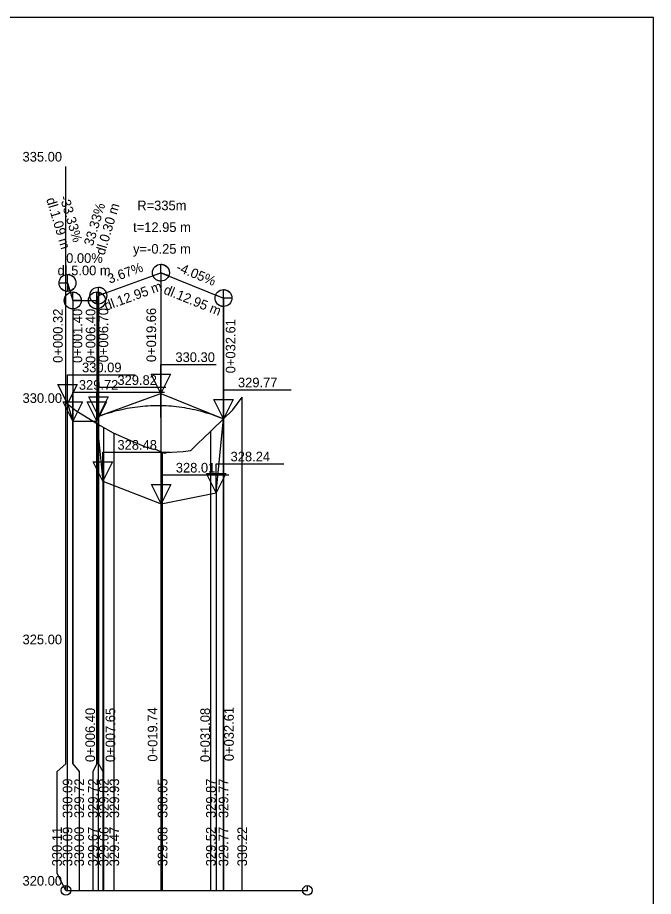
# Model space of a CAD drawing. Extents: x -559854 to -559644, y -1163295 to -1162998.
# Drawn here: x -559776.1 to -559644.4, y -1163179.8 to -1162997.7 of the extents above; entities that cross this region are included whole.
import ezdxf

# ---------------------------------------------------------------- set-up
doc = ezdxf.new("R2010")
doc.units = 0
for name, color, linetype in [('13', 7, 'Continuous'), ('14', 7, 'Continuous'), ('16', 7, 'Continuous'), ('46', 7, 'Continuous'), ('56', 7, 'Continuous'), ('8', 7, 'Continuous'), ('_rám PH2 a PH4', 7, 'Continuous')]:
    doc.layers.add(name, color=color, linetype=linetype)

msp = doc.modelspace()

# ---------------------------------------------------------------- linework, layer by layer
for p, q in [((-559644.4, -1162997.74), (-559854.4, -1162997.74)), ((-559644.4, -1163294.74), (-559644.4, -1162997.74)), ((-559752.86, -1163077.97), (-559746.38, -1163075.59)), ((-559746.38, -1163080.59), (-559746.38, -1163075.59)), ((-559746.38, -1163075.59), (-559739.91, -1163078.22)), ((-559729.55, -1163178.57), (-559729.55, -1163076.37)), ((-559765.72, -1163178.57), (-559765.72, -1163077.67)), ((-559765.72, -1163077.72), (-559764.64, -1163081.34)), ((-559764.64, -1163152.32), (-559764.64, -1163078.57)), ((-559759.64, -1163081.34), (-559759.34, -1163080.34)), ((-559759.34, -1163080.34), (-559759.33, -1163080.34)), ((-559759.34, -1163080.34), (-559759.33, -1163080.34)), ((-559734.96, -1163096.18), (-559733.43, -1163080.84)), ((-559733.43, -1163080.84), (-559733.43, -1163080.84)), ((-559733.43, -1163080.84), (-559733.43, -1163080.84)), ((-559733.43, -1163178.57), (-559733.43, -1163080.87)), ((-559733.43, -1163178.57), (-559733.43, -1163080.87)), ((-559764.64, -1163081.34), (-559759.64, -1163081.34)), ((-559759.64, -1163081.34), (-559758.39, -1163093.77)), ((-559759.64, -1163152.32), (-559759.64, -1163081.87)), ((-559759.34, -1163152.32), (-559759.34, -1163081.97)), ((-559759.33, -1163178.57), (-559759.33, -1163081.97)), ((-559758.22, -1163178.57), (-559758.22, -1163082.68)), ((-559756.04, -1163178.57), (-559756.04, -1163083.87)), ((-559736.04, -1163178.57), (-559736.04, -1163083.37)), ((-559746.04, -1163178.57), (-559746.04, -1163087.77)), ((-559758.39, -1163093.77), (-559746.3, -1163098.49)), ((-559746.3, -1163098.49), (-559734.96, -1163096.18))]:
    msp.add_line(p, q)
for points in [[(-559766.04, -1163077.46), (-559764.01, -1163079.13), (-559758.94, -1163082.26), (-559756.27, -1163083.79), (-559752.18, -1163085.57), (-559749.89, -1163086.54), (-559749.64, -1163086.64), (-559748.19, -1163087.06), (-559747.74, -1163087.12), (-559747.6, -1163087.18), (-559745.64, -1163087.97), (-559745.31, -1163087.88), (-559745.23, -1163087.86), (-559743.02, -1163087.72), (-559741.79, -1163087.63), (-559741.79, -1163087.63), (-559740.73, -1163087.5), (-559740.32, -1163087.45), (-559740.2, -1163087.41), (-559738.44, -1163085.72), (-559737.86, -1163085.17), (-559731.52, -1163078.98), (-559729.55, -1163076.35)], [(-559767.9, -1163153.91), (-559766.04, -1163152.32), (-559766.04, -1163077.47)], [(-559759.33, -1163080.34), (-559758.79, -1163080.15), (-559758.25, -1163079.96), (-559757.71, -1163079.79), (-559757.17, -1163079.62), (-559756.63, -1163079.46), (-559756.09, -1163079.31), (-559755.55, -1163079.17), (-559755.01, -1163079.04), (-559754.47, -1163078.91), (-559753.94, -1163078.8), (-559753.4, -1163078.69), (-559752.86, -1163078.59), (-559752.32, -1163078.5), (-559751.78, -1163078.42), (-559751.24, -1163078.35), (-559750.7, -1163078.29), (-559750.16, -1163078.23), (-559749.62, -1163078.19), (-559749.08, -1163078.15), (-559748.54, -1163078.12), (-559748, -1163078.1), (-559747.46, -1163078.09), (-559746.92, -1163078.09), (-559745.84, -1163078.11), (-559745.3, -1163078.13), (-559744.76, -1163078.16), (-559744.22, -1163078.2), (-559743.68, -1163078.25), (-559743.14, -1163078.31), (-559742.6, -1163078.38), (-559742.06, -1163078.45), (-559741.52, -1163078.54), (-559740.99, -1163078.63), (-559740.45, -1163078.73), (-559739.91, -1163078.84), (-559739.37, -1163078.96), (-559738.83, -1163079.09), (-559738.29, -1163079.22), (-559737.75, -1163079.37), (-559737.21, -1163079.52), (-559736.67, -1163079.68), (-559736.13, -1163079.86), (-559735.59, -1163080.04), (-559735.05, -1163080.22), (-559734.51, -1163080.42), (-559733.97, -1163080.63), (-559733.43, -1163080.84)], [(-559759.33, -1163080.34), (-559758.79, -1163080.15), (-559758.25, -1163079.96), (-559757.71, -1163079.79), (-559757.17, -1163079.62), (-559756.63, -1163079.46), (-559756.09, -1163079.31), (-559755.55, -1163079.17), (-559755.01, -1163079.04), (-559754.47, -1163078.91), (-559753.94, -1163078.8), (-559753.4, -1163078.69), (-559752.86, -1163078.59), (-559752.32, -1163078.5), (-559751.78, -1163078.42), (-559751.24, -1163078.35), (-559750.7, -1163078.29), (-559750.16, -1163078.23), (-559749.62, -1163078.19), (-559749.08, -1163078.15), (-559748.54, -1163078.12), (-559748, -1163078.1), (-559747.46, -1163078.09), (-559746.92, -1163078.09), (-559745.84, -1163078.11), (-559745.3, -1163078.13), (-559744.76, -1163078.16), (-559744.22, -1163078.2), (-559743.68, -1163078.25), (-559743.14, -1163078.31), (-559742.6, -1163078.38), (-559742.06, -1163078.45), (-559741.52, -1163078.54), (-559740.99, -1163078.63), (-559740.45, -1163078.73), (-559739.91, -1163078.84), (-559739.37, -1163078.96), (-559738.83, -1163079.09), (-559738.29, -1163079.22), (-559737.75, -1163079.37), (-559737.21, -1163079.52), (-559736.67, -1163079.68), (-559736.13, -1163079.86), (-559735.59, -1163080.04), (-559735.05, -1163080.22), (-559734.51, -1163080.42), (-559733.97, -1163080.63), (-559733.43, -1163080.84)], [(-559766.04, -1163178.57), (-559767.9, -1163175.05), (-559767.9, -1163153.91)]]:
    msp.add_lwpolyline(points)
for centre in [(-559766.04, -1163178.57), (-559716.04, -1163178.57)]:
    msp.add_circle(centre, 1)
at = {"layer": '14'}
for p, q in [((-559759.34, -1163055.34), (-559746.38, -1163050.59)), ((-559746.38, -1163050.59), (-559746.38, -1163178.57)), ((-559746.38, -1163050.59), (-559733.43, -1163055.84)), ((-559765.72, -1163052.72), (-559765.72, -1163052.72)), ((-559765.72, -1163052.72), (-559764.64, -1163056.34)), ((-559759.64, -1163056.34), (-559759.34, -1163055.34)), ((-559759.34, -1163055.34), (-559759.34, -1163152.32)), ((-559764.64, -1163056.34), (-559764.64, -1163152.32)), ((-559764.64, -1163056.34), (-559759.64, -1163056.34)), ((-559733.43, -1163055.84), (-559733.43, -1163178.57)), ((-559759.34, -1163080.34), (-559746.38, -1163075.59)), ((-559746.38, -1163075.59), (-559746.38, -1163178.57)), ((-559746.38, -1163075.59), (-559733.43, -1163080.84)), ((-559765.72, -1163077.72), (-559764.64, -1163081.34)), ((-559765.72, -1163077.72), (-559764.64, -1163081.34)), ((-559765.72, -1163077.72), (-559765.72, -1163077.72)), ((-559765.72, -1163077.72), (-559764.64, -1163081.34)), ((-559759.64, -1163081.34), (-559759.34, -1163080.34)), ((-559759.64, -1163081.34), (-559759.34, -1163080.34)), ((-559759.64, -1163081.34), (-559759.34, -1163080.34)), ((-559759.34, -1163080.34), (-559759.33, -1163080.34)), ((-559759.34, -1163080.34), (-559759.33, -1163080.34)), ((-559759.34, -1163080.34), (-559759.34, -1163152.32)), ((-559734.96, -1163096.18), (-559733.43, -1163080.84)), ((-559734.96, -1163096.18), (-559733.43, -1163080.84)), ((-559734.96, -1163096.18), (-559733.43, -1163080.84)), ((-559733.43, -1163080.84), (-559733.43, -1163080.84)), ((-559733.43, -1163080.84), (-559733.43, -1163080.84)), ((-559733.43, -1163080.84), (-559733.43, -1163178.57)), ((-559733.43, -1163080.84), (-559733.43, -1163178.57)), ((-559764.64, -1163081.34), (-559759.64, -1163081.34)), ((-559764.64, -1163081.34), (-559759.64, -1163081.34)), ((-559764.64, -1163081.34), (-559764.64, -1163152.32)), ((-559764.64, -1163081.34), (-559759.64, -1163081.34)), ((-559759.64, -1163081.34), (-559758.39, -1163093.77)), ((-559759.64, -1163081.34), (-559758.39, -1163093.77)), ((-559759.64, -1163081.34), (-559759.64, -1163081.34)), ((-559759.64, -1163081.34), (-559758.39, -1163093.77)), ((-559758.39, -1163093.77), (-559746.3, -1163098.49)), ((-559758.39, -1163093.77), (-559746.3, -1163098.49)), ((-559746.3, -1163098.49), (-559734.96, -1163096.18)), ((-559746.3, -1163098.49), (-559734.96, -1163096.18)), ((-559734.96, -1163096.18), (-559734.96, -1163178.57)), ((-559746.3, -1163098.49), (-559746.3, -1163178.57)), ((-559760.46, -1163153.91), (-559760.46, -1163178.57))]:
    msp.add_line(p, q, dxfattribs=at)
for points in [[(-559759.64, -1163056.34), (-559759.64, -1163152.32), (-559760.46, -1163153.91)], [(-559759.33, -1163080.34), (-559758.79, -1163080.15), (-559758.25, -1163079.96), (-559757.71, -1163079.79), (-559757.17, -1163079.62), (-559756.63, -1163079.46), (-559756.09, -1163079.31), (-559755.55, -1163079.17), (-559755.01, -1163079.04), (-559754.47, -1163078.91), (-559753.94, -1163078.8), (-559753.4, -1163078.69), (-559752.86, -1163078.59), (-559752.32, -1163078.5), (-559751.78, -1163078.42), (-559751.24, -1163078.35), (-559750.7, -1163078.29), (-559750.16, -1163078.23), (-559749.62, -1163078.19), (-559749.08, -1163078.15), (-559748.54, -1163078.12), (-559748, -1163078.1), (-559747.46, -1163078.09), (-559746.92, -1163078.09), (-559745.84, -1163078.11), (-559745.3, -1163078.13), (-559744.76, -1163078.16), (-559744.22, -1163078.2), (-559743.68, -1163078.25), (-559743.14, -1163078.31), (-559742.6, -1163078.38), (-559742.06, -1163078.45), (-559741.52, -1163078.54), (-559740.99, -1163078.63), (-559740.45, -1163078.73), (-559739.91, -1163078.84), (-559739.37, -1163078.96), (-559738.83, -1163079.09), (-559738.29, -1163079.22), (-559737.75, -1163079.37), (-559737.21, -1163079.52), (-559736.67, -1163079.68), (-559736.13, -1163079.86), (-559735.59, -1163080.04), (-559735.05, -1163080.22), (-559734.51, -1163080.42), (-559733.97, -1163080.63), (-559733.43, -1163080.84)], [(-559764.64, -1163152.32), (-559763.31, -1163153.91), (-559763.31, -1163178.57)], [(-559759.34, -1163152.32), (-559758.39, -1163153.91), (-559758.39, -1163178.57)]]:
    msp.add_lwpolyline(points, dxfattribs=at)
at = {"layer": '16'}
msp.add_lwpolyline([(-559759.33, -1163080.34), (-559758.79, -1163080.15), (-559758.25, -1163079.96), (-559757.71, -1163079.79), (-559757.17, -1163079.62), (-559756.63, -1163079.46), (-559756.09, -1163079.31), (-559755.55, -1163079.17), (-559755.01, -1163079.04), (-559754.47, -1163078.91), (-559753.94, -1163078.8), (-559753.4, -1163078.69), (-559752.86, -1163078.59), (-559752.32, -1163078.5), (-559751.78, -1163078.42), (-559751.24, -1163078.35), (-559750.7, -1163078.29), (-559750.16, -1163078.23), (-559749.62, -1163078.19), (-559749.08, -1163078.15), (-559748.54, -1163078.12), (-559748, -1163078.1), (-559747.46, -1163078.09), (-559746.92, -1163078.09), (-559745.84, -1163078.11), (-559745.3, -1163078.13), (-559744.76, -1163078.16), (-559744.22, -1163078.2), (-559743.68, -1163078.25), (-559743.14, -1163078.31), (-559742.6, -1163078.38), (-559742.06, -1163078.45), (-559741.52, -1163078.54), (-559740.99, -1163078.63), (-559740.45, -1163078.73), (-559739.91, -1163078.84), (-559739.37, -1163078.96), (-559738.83, -1163079.09), (-559738.29, -1163079.22), (-559737.75, -1163079.37), (-559737.21, -1163079.52), (-559736.67, -1163079.68), (-559736.13, -1163079.86), (-559735.59, -1163080.04), (-559735.05, -1163080.22), (-559734.51, -1163080.42), (-559733.97, -1163080.63), (-559733.43, -1163080.84)], dxfattribs=at)
at = {"layer": '46'}
for points in [[(-559746.38, -1163050.59), (-559746.38, -1163048.84), (-559746.27, -1163048.85), (-559746.16, -1163048.86), (-559746.05, -1163048.87), (-559745.94, -1163048.9), (-559745.83, -1163048.93), (-559745.72, -1163048.97), (-559745.62, -1163049.02), (-559745.52, -1163049.07), (-559745.43, -1163049.13), (-559745.33, -1163049.19), (-559745.25, -1163049.26), (-559745.16, -1163049.33), (-559745.09, -1163049.42), (-559745.01, -1163049.5), (-559744.95, -1163049.59), (-559744.88, -1163049.68), (-559744.83, -1163049.78), (-559744.78, -1163049.88), (-559744.74, -1163049.99), (-559744.7, -1163050.09), (-559744.68, -1163050.2), (-559744.65, -1163050.31), (-559744.64, -1163050.42), (-559744.63, -1163050.54), (-559744.63, -1163050.65), (-559744.64, -1163050.76), (-559744.65, -1163050.87), (-559744.68, -1163050.98), (-559744.7, -1163051.09), (-559744.74, -1163051.2), (-559744.76, -1163051.25), (-559746.38, -1163050.59), (-559746.38, -1163052.34), (-559746.49, -1163052.34), (-559746.61, -1163052.33), (-559746.72, -1163052.31), (-559746.83, -1163052.28), (-559746.93, -1163052.25), (-559747.04, -1163052.21), (-559747.14, -1163052.17), (-559747.24, -1163052.12), (-559747.34, -1163052.06), (-559747.43, -1163051.99), (-559747.52, -1163051.92), (-559747.6, -1163051.85), (-559747.68, -1163051.77), (-559747.75, -1163051.68), (-559747.82, -1163051.59), (-559747.88, -1163051.5), (-559747.93, -1163051.4), (-559747.98, -1163051.3), (-559748.02, -1163051.2), (-559748.02, -1163051.19)], [(-559765.72, -1163052.72), (-559765.72, -1163050.97), (-559765.61, -1163050.97), (-559765.5, -1163050.98), (-559765.39, -1163051), (-559765.28, -1163051.02), (-559765.17, -1163051.06), (-559765.07, -1163051.1), (-559764.96, -1163051.14), (-559764.86, -1163051.19), (-559764.77, -1163051.25), (-559764.68, -1163051.32), (-559764.59, -1163051.38), (-559764.51, -1163051.46), (-559764.43, -1163051.54), (-559764.35, -1163051.63), (-559764.29, -1163051.72), (-559764.23, -1163051.81), (-559764.17, -1163051.91), (-559764.12, -1163052.01), (-559764.08, -1163052.11), (-559764.05, -1163052.22), (-559764.02, -1163052.33), (-559764, -1163052.44), (-559763.98, -1163052.55), (-559763.97, -1163052.66), (-559763.97, -1163052.77), (-559763.98, -1163052.89), (-559764, -1163053), (-559764.02, -1163053.11), (-559764.05, -1163053.22), (-559764.08, -1163053.32), (-559764.12, -1163053.43), (-559764.17, -1163053.53), (-559764.23, -1163053.62), (-559764.29, -1163053.72), (-559764.35, -1163053.81), (-559764.43, -1163053.89), (-559764.51, -1163053.97), (-559764.59, -1163054.05), (-559764.68, -1163054.12), (-559764.77, -1163054.18), (-559764.86, -1163054.24), (-559764.96, -1163054.29), (-559765.07, -1163054.34), (-559765.17, -1163054.38), (-559765.22, -1163054.39), (-559765.72, -1163052.72), (-559765.72, -1163054.47), (-559765.84, -1163054.46), (-559765.95, -1163054.45), (-559766.06, -1163054.44), (-559766.17, -1163054.41), (-559766.27, -1163054.38), (-559766.38, -1163054.34), (-559766.48, -1163054.29), (-559766.58, -1163054.24), (-559766.68, -1163054.18), (-559766.77, -1163054.12), (-559766.86, -1163054.05), (-559766.94, -1163053.97), (-559767.02, -1163053.89), (-559767.09, -1163053.81), (-559767.16, -1163053.72), (-559767.22, -1163053.62), (-559767.27, -1163053.53), (-559767.32, -1163053.43), (-559767.37, -1163053.32), (-559767.4, -1163053.22), (-559767.43, -1163053.11), (-559767.45, -1163053), (-559767.46, -1163052.89), (-559767.47, -1163052.77), (-559767.47, -1163052.72)], [(-559759.34, -1163055.34), (-559759.34, -1163053.59), (-559759.22, -1163053.6), (-559759.11, -1163053.61), (-559759, -1163053.62), (-559758.89, -1163053.65), (-559758.78, -1163053.68), (-559758.68, -1163053.72), (-559758.58, -1163053.77), (-559758.48, -1163053.82), (-559758.38, -1163053.88), (-559758.29, -1163053.94), (-559758.2, -1163054.01), (-559758.12, -1163054.09), (-559758.04, -1163054.17), (-559757.97, -1163054.25), (-559757.9, -1163054.34), (-559757.84, -1163054.44), (-559757.78, -1163054.53), (-559757.74, -1163054.63), (-559757.69, -1163054.74), (-559757.69, -1163054.74), (-559759.34, -1163055.34), (-559759.34, -1163057.09), (-559759.45, -1163057.09), (-559759.56, -1163057.08), (-559759.67, -1163057.06), (-559759.78, -1163057.04), (-559759.84, -1163057.02)], [(-559764.64, -1163056.34), (-559764.64, -1163054.59), (-559764.52, -1163054.6), (-559764.41, -1163054.61), (-559764.3, -1163054.62), (-559764.19, -1163054.65), (-559764.08, -1163054.68), (-559763.98, -1163054.72), (-559763.88, -1163054.77), (-559763.78, -1163054.82), (-559763.68, -1163054.88), (-559763.59, -1163054.94), (-559763.5, -1163055.01), (-559763.42, -1163055.09), (-559763.34, -1163055.17), (-559763.27, -1163055.25), (-559763.2, -1163055.34), (-559763.14, -1163055.44), (-559763.08, -1163055.53), (-559763.04, -1163055.63), (-559762.99, -1163055.74), (-559762.96, -1163055.84), (-559762.93, -1163055.95), (-559762.91, -1163056.06), (-559762.89, -1163056.17), (-559762.89, -1163056.29), (-559762.89, -1163056.34), (-559764.64, -1163056.34), (-559764.64, -1163058.09), (-559764.75, -1163058.09), (-559764.86, -1163058.08), (-559764.97, -1163058.06), (-559765.08, -1163058.04), (-559765.19, -1163058), (-559765.29, -1163057.96), (-559765.39, -1163057.92), (-559765.49, -1163057.87), (-559765.59, -1163057.81), (-559765.68, -1163057.75), (-559765.77, -1163057.68), (-559765.85, -1163057.6), (-559765.93, -1163057.52), (-559766, -1163057.43), (-559766.07, -1163057.34), (-559766.13, -1163057.25), (-559766.19, -1163057.15), (-559766.24, -1163057.05), (-559766.28, -1163056.95), (-559766.31, -1163056.84), (-559766.34, -1163056.73), (-559766.36, -1163056.62), (-559766.38, -1163056.51), (-559766.38, -1163056.4), (-559766.38, -1163056.29), (-559766.38, -1163056.17), (-559766.36, -1163056.06), (-559766.34, -1163055.95), (-559766.31, -1163055.84), (-559766.28, -1163055.74), (-559766.24, -1163055.63), (-559766.19, -1163055.53), (-559766.13, -1163055.44), (-559766.07, -1163055.34), (-559766, -1163055.25), (-559765.93, -1163055.17), (-559765.85, -1163055.09), (-559765.77, -1163055.01), (-559765.68, -1163054.94), (-559765.59, -1163054.88), (-559765.49, -1163054.82), (-559765.39, -1163054.77), (-559765.29, -1163054.72), (-559765.19, -1163054.68), (-559765.14, -1163054.67)], [(-559759.64, -1163056.34), (-559759.64, -1163054.59), (-559759.52, -1163054.6), (-559759.41, -1163054.61), (-559759.3, -1163054.62), (-559759.19, -1163054.65), (-559759.13, -1163054.67), (-559759.64, -1163056.34), (-559759.64, -1163058.09), (-559759.75, -1163058.09), (-559759.86, -1163058.08), (-559759.97, -1163058.06), (-559760.08, -1163058.04), (-559760.19, -1163058), (-559760.29, -1163057.96), (-559760.39, -1163057.92), (-559760.49, -1163057.87), (-559760.59, -1163057.81), (-559760.68, -1163057.75), (-559760.77, -1163057.68), (-559760.85, -1163057.6), (-559760.93, -1163057.52), (-559761, -1163057.43), (-559761.07, -1163057.34), (-559761.13, -1163057.25), (-559761.19, -1163057.15), (-559761.24, -1163057.05), (-559761.28, -1163056.95), (-559761.31, -1163056.84), (-559761.34, -1163056.73), (-559761.36, -1163056.62), (-559761.38, -1163056.51), (-559761.38, -1163056.4), (-559761.39, -1163056.34)], [(-559733.43, -1163055.84), (-559733.43, -1163054.09), (-559733.32, -1163054.1), (-559733.2, -1163054.11), (-559733.09, -1163054.12), (-559732.98, -1163054.15), (-559732.88, -1163054.18), (-559732.77, -1163054.22), (-559732.67, -1163054.27), (-559732.57, -1163054.32), (-559732.47, -1163054.38), (-559732.38, -1163054.44), (-559732.29, -1163054.51), (-559732.21, -1163054.59), (-559732.13, -1163054.67), (-559732.06, -1163054.75), (-559731.99, -1163054.84), (-559731.93, -1163054.94), (-559731.88, -1163055.03), (-559731.83, -1163055.13), (-559731.78, -1163055.24), (-559731.75, -1163055.34), (-559731.72, -1163055.45), (-559731.7, -1163055.56), (-559731.69, -1163055.67), (-559731.68, -1163055.79), (-559731.68, -1163055.84), (-559733.43, -1163055.84), (-559733.43, -1163057.59), (-559733.54, -1163057.59), (-559733.65, -1163057.58), (-559733.76, -1163057.56), (-559733.87, -1163057.54), (-559733.98, -1163057.5), (-559734.08, -1163057.46), (-559734.19, -1163057.42), (-559734.29, -1163057.37), (-559734.38, -1163057.31), (-559734.47, -1163057.25), (-559734.56, -1163057.18), (-559734.64, -1163057.1), (-559734.72, -1163057.02), (-559734.8, -1163056.93), (-559734.86, -1163056.84), (-559734.92, -1163056.75), (-559734.98, -1163056.65), (-559735.03, -1163056.55), (-559735.07, -1163056.45), (-559735.1, -1163056.34), (-559735.13, -1163056.23), (-559735.15, -1163056.12), (-559735.17, -1163056.01), (-559735.18, -1163055.9), (-559735.18, -1163055.79), (-559735.17, -1163055.67), (-559735.15, -1163055.56), (-559735.13, -1163055.45), (-559735.1, -1163055.34), (-559735.07, -1163055.24), (-559735.05, -1163055.19)], [(-559746.38, -1163075.59), (-559748.38, -1163071.59), (-559744.38, -1163071.59)], [(-559765.72, -1163077.72), (-559767.72, -1163073.72), (-559763.72, -1163073.72)], [(-559764.64, -1163081.34), (-559766.64, -1163077.34), (-559762.64, -1163077.34)], [(-559759.64, -1163081.34), (-559761.64, -1163077.34), (-559757.64, -1163077.34)], [(-559759.64, -1163081.34), (-559761.64, -1163077.34), (-559757.64, -1163077.34)], [(-559759.34, -1163080.34), (-559761.34, -1163076.34), (-559757.34, -1163076.34)], [(-559733.43, -1163080.84), (-559735.43, -1163076.84), (-559731.43, -1163076.84)], [(-559733.43, -1163080.84), (-559735.43, -1163076.84), (-559731.43, -1163076.84)], [(-559758.39, -1163093.77), (-559760.39, -1163089.77), (-559756.39, -1163089.77)], [(-559734.96, -1163096.18), (-559736.96, -1163092.18), (-559732.96, -1163092.18)], [(-559746.3, -1163098.49), (-559748.3, -1163094.49), (-559744.3, -1163094.49)]]:
    msp.add_lwpolyline(points, close=True, dxfattribs=at)
for centre in [(-559746.38, -1163050.59), (-559765.72, -1163052.72), (-559759.34, -1163055.34), (-559764.64, -1163056.34), (-559759.64, -1163056.34), (-559733.43, -1163055.84)]:
    msp.add_circle(centre, 1.75, dxfattribs=at)
at = {"layer": '56'}
for p, q in [((-559766.04, -1163152.32), (-559766.04, -1163028.57)), ((-559766.04, -1163178.57), (-559766.04, -1163177.57)), ((-559766.04, -1163178.57), (-559716.04, -1163178.57)), ((-559716.04, -1163178.57), (-559716.04, -1163177.57))]:
    msp.add_line(p, q, dxfattribs=at)
at = {"layer": '8'}
for p, q in [((-559759.33, -1163080.34), (-559759.33, -1163055.34)), ((-559733.43, -1163080.84), (-559733.43, -1163055.84)), ((-559746.38, -1163075.59), (-559746.38, -1163069.59)), ((-559746.38, -1163069.59), (-559734.93, -1163069.59)), ((-559765.72, -1163077.72), (-559765.72, -1163071.72)), ((-559765.72, -1163071.72), (-559751.72, -1163071.72)), ((-559764.64, -1163081.34), (-559764.64, -1163075.34)), ((-559764.64, -1163075.34), (-559750.64, -1163075.34)), ((-559759.64, -1163081.34), (-559759.64, -1163075.34)), ((-559759.64, -1163075.34), (-559745.64, -1163075.34)), ((-559759.64, -1163081.34), (-559759.64, -1163075.34)), ((-559759.64, -1163075.34), (-559745.64, -1163075.34)), ((-559759.34, -1163080.34), (-559759.34, -1163074.34)), ((-559759.34, -1163074.34), (-559745.34, -1163074.34)), ((-559733.43, -1163080.84), (-559733.43, -1163074.84)), ((-559733.43, -1163074.84), (-559719.43, -1163074.84)), ((-559733.43, -1163080.84), (-559733.43, -1163074.84)), ((-559733.43, -1163074.84), (-559719.43, -1163074.84)), ((-559758.39, -1163093.77), (-559758.39, -1163087.77)), ((-559758.39, -1163087.77), (-559744.39, -1163087.77)), ((-559734.96, -1163096.18), (-559734.96, -1163090.18)), ((-559734.96, -1163090.18), (-559720.96, -1163090.18)), ((-559746.3, -1163098.49), (-559746.3, -1163092.49)), ((-559746.3, -1163092.49), (-559732.3, -1163092.49))]:
    msp.add_line(p, q, dxfattribs=at)
at = {"layer": '_rám PH2 a PH4'}
msp.add_line((-559758.39, -1163093.77), (-559758.39, -1163178.57), dxfattribs=at)

# ---------------------------------------------------------------- texts
for s, p in [('330.09', (-559764.72, -1163163.57)), ('329.72', (-559762.31, -1163163.57)), ('329.72', (-559759.46, -1163163.57)), ('329.82', (-559757.22, -1163163.57)), ('329.93', (-559755.04, -1163163.57)), ('330.05', (-559745.04, -1163163.57)), ('329.87', (-559735.04, -1163163.57)), ('329.77', (-559732.43, -1163163.57)), ('330.11', (-559766.9, -1163173.57)), ('330.09', (-559764.72, -1163173.57)), ('330.00', (-559762.31, -1163173.57)), ('329.67', (-559759.46, -1163173.57)), ('329.66', (-559757.22, -1163173.57)), ('329.47', (-559755.04, -1163173.57)), ('329.08', (-559745.04, -1163173.57)), ('329.52', (-559735.04, -1163173.57)), ('329.77', (-559732.43, -1163173.57)), ('330.22', (-559728.55, -1163173.57))]:
    msp.add_text(s, height=2, rotation=90).set_placement(p)
at = {"layer": '13'}
for s, p in [('335.00', (-559775.04, -1163027.57)), ('335.00', (-559775.04, -1163027.57)), ('330.00', (-559775.04, -1163077.57)), ('325.00', (-559775.04, -1163127.57)), ('320.00', (-559775.04, -1163177.57))]:
    msp.add_text(s, height=2, dxfattribs=at).set_placement(p)
at = {"layer": '16'}
for s, rotation, p in [('dl.1.09 m', 286.6992, (-559770.16, -1163035.36)), ('-33.33%', 286.6992, (-559767.38, -1163034.94)), ('33.33%', 73.3008, (-559760.48, -1163045.19)), ('dl.0.30 m', 73.3008, (-559758.09, -1163047.09)), ('3.67%', 20.1406, (-559757.01, -1163052.89)), ('-4.05%', 337.9349, (-559743.36, -1163050.2)), ('dl.12.95 m', 20.1406, (-559757.69, -1163058.47)), ('dl.12.95 m', 337.9349, (-559745.98, -1163054.87)), ('0+000.32', 90, (-559766.72, -1163069.27)), ('0+001.40', 90, (-559762.68, -1163069.3)), ('0+006.40', 90, (-559759.95, -1163069.3)), ('0+006.70', 90, (-559757.29, -1163069.15)), ('0+019.66', 90, (-559747.38, -1163069.11)), ('0+032.61', 90, (-559730.96, -1163071.43)), ('0+006.40', 90, (-559760.03, -1163151.97)), ('0+007.65', 90, (-559755.84, -1163151.97)), ('0+019.74', 90, (-559747.11, -1163151.88)), ('0+031.08', 90, (-559736.23, -1163151.97)), ('0+032.61', 90, (-559731.29, -1163151.78))]:
    msp.add_text(s, height=2, rotation=rotation, dxfattribs=at).set_placement(p)
for s, p in [('R=335m', (-559751.28, -1163037.66)), ('t=12.95 m', (-559752.15, -1163042.16)), ('y=-0.25 m', (-559752.15, -1163046.66)), ('0.00%', (-559766.01, -1163048.56)), ('dl.5.00 m', (-559767.79, -1163051.12)), ('330.30', (-559743.38, -1163069.09)), ('330.09', (-559762.72, -1163071.22)), ('329.82', (-559755.39, -1163073.84)), ('329.72', (-559763.38, -1163074.84)), ('329.77', (-559730.43, -1163074.34)), ('329.77', (-559730.43, -1163074.34)), ('328.48', (-559755.39, -1163087.27)), ('328.24', (-559731.96, -1163089.68)), ('328.01', (-559743.3, -1163091.99))]:
    msp.add_text(s, height=2, dxfattribs=at).set_placement(p)

doc.saveas('drawing.dxf')
